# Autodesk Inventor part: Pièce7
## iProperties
Shininess: 64.0
Length Units: 11269
Angle Units: 11279
Time Units: 11290
Mass Units: 11283
Length Display Precision: 3
Angle Display Precision: 2
Compacted: True
Part Number: Pièce7
Document SubType Name: Modeling
Created: 2004-09
Material: Par défaut
Designer: lolo
Density: 0.0
Volumn: 0.0
Area: 0.0
PropertySet Name: Model Information
Control State: 0
Master: False
Checked Out: False
Author: lolo
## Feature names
1. Extrusion1
